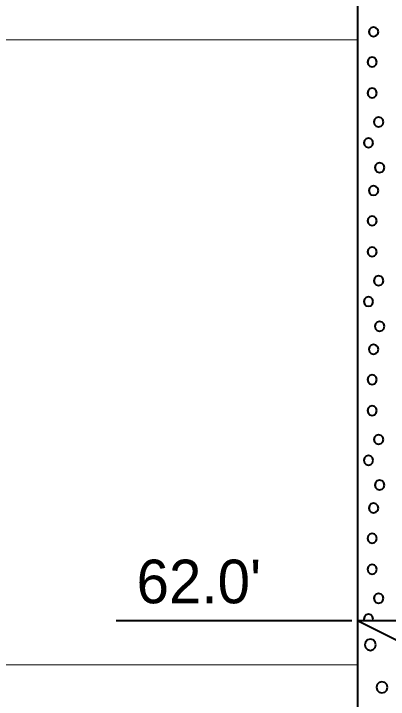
# Model space of a CAD drawing. Extents: x -76 to 974, y -1080 to -735.
# Drawn here: x 752 to 757.99, y -992.64 to -981.67 of the extents above; entities that cross this region are included whole.
import ezdxf

# ---------------------------------------------------------------- set-up
doc = ezdxf.new("R2010")
doc.units = 0
doc.header["$LTSCALE"] = 0.36
doc.layers.add('27', color=7, linetype='Continuous', lineweight=40)
doc.layers.add('7', color=7, linetype='Continuous', lineweight=13)

msp = doc.modelspace()

# ---------------------------------------------------------------- linework, layer by layer
at = {"layer": '27'}
for p, q in [((757.4958, -981.3789), (757.4958, -991.3789)), ((753.6395, -991.3789), (757.4069, -991.3789)), ((757.4958, -991.3789), (759.9958, -991.3789)), ((757.4958, -991.3789), (759.9958, -992.6289)), ((757.4958, -991.3789), (757.4958, -996.3789))]:
    msp.add_line(p, q, dxfattribs=at)
for points in [[(757.8315, -981.9594), (757.8213, -981.9213), (757.7934, -981.8934), (757.7553, -981.8832), (757.7172, -981.8934), (757.6893, -981.9213), (757.6791, -981.9594), (757.6893, -981.9975), (757.7172, -982.0254), (757.7553, -982.0356), (757.7934, -982.0254), (757.8213, -981.9975)], [(757.8086, -982.4438), (757.7984, -982.4057), (757.7705, -982.3778), (757.7324, -982.3676), (757.6943, -982.3778), (757.6664, -982.4057), (757.6562, -982.4438), (757.6664, -982.4819), (757.6943, -982.5097), (757.7324, -982.52), (757.7705, -982.5097), (757.7984, -982.4819)], [(757.8086, -982.9396), (757.7984, -982.9015), (757.7705, -982.8736), (757.7324, -982.8634), (757.6943, -982.8736), (757.6664, -982.9015), (757.6562, -982.9396), (757.6664, -982.9777), (757.6943, -983.0055), (757.7324, -983.0158), (757.7705, -983.0055), (757.7984, -982.9777)], [(757.9116, -983.4023), (757.9014, -983.3642), (757.8735, -983.3363), (757.8354, -983.3261), (757.7973, -983.3363), (757.7694, -983.3642), (757.7592, -983.4023), (757.7694, -983.4404), (757.7973, -983.4683), (757.8354, -983.4785), (757.8735, -983.4683), (757.9014, -983.4404)], [(757.7501, -983.7354), (757.7399, -983.6973), (757.712, -983.6694), (757.6739, -983.6592), (757.6358, -983.6694), (757.608, -983.6973), (757.5977, -983.7354), (757.608, -983.7735), (757.6358, -983.8014), (757.6739, -983.8116), (757.712, -983.8014), (757.7399, -983.7735)], [(757.9277, -984.1316), (757.9175, -984.0935), (757.8896, -984.0656), (757.8515, -984.0554), (757.8134, -984.0656), (757.7855, -984.0935), (757.7753, -984.1316), (757.7855, -984.1697), (757.8134, -984.1975), (757.8515, -984.2078), (757.8896, -984.1975), (757.9175, -984.1697)], [(757.8315, -984.4994), (757.8213, -984.4613), (757.7934, -984.4334), (757.7553, -984.4232), (757.7172, -984.4334), (757.6893, -984.4613), (757.6791, -984.4994), (757.6893, -984.5375), (757.7172, -984.5654), (757.7553, -984.5756), (757.7934, -984.5654), (757.8213, -984.5375)], [(757.8086, -984.9838), (757.7984, -984.9457), (757.7705, -984.9178), (757.7324, -984.9076), (757.6943, -984.9178), (757.6664, -984.9457), (757.6562, -984.9838), (757.6664, -985.0219), (757.6943, -985.0497), (757.7324, -985.06), (757.7705, -985.0497), (757.7984, -985.0219)], [(757.8086, -985.4796), (757.7984, -985.4415), (757.7705, -985.4136), (757.7324, -985.4034), (757.6943, -985.4136), (757.6664, -985.4415), (757.6562, -985.4796), (757.6664, -985.5177), (757.6943, -985.5455), (757.7324, -985.5558), (757.7705, -985.5455), (757.7984, -985.5177)], [(757.9116, -985.9423), (757.9014, -985.9042), (757.8735, -985.8763), (757.8354, -985.8661), (757.7973, -985.8763), (757.7694, -985.9042), (757.7592, -985.9423), (757.7694, -985.9804), (757.7973, -986.0083), (757.8354, -986.0185), (757.8735, -986.0083), (757.9014, -985.9804)], [(757.7501, -986.2754), (757.7399, -986.2373), (757.712, -986.2094), (757.6739, -986.1992), (757.6358, -986.2094), (757.608, -986.2373), (757.5977, -986.2754), (757.608, -986.3135), (757.6358, -986.3414), (757.6739, -986.3516), (757.712, -986.3414), (757.7399, -986.3135)], [(757.9277, -986.6716), (757.9175, -986.6335), (757.8896, -986.6056), (757.8515, -986.5954), (757.8134, -986.6056), (757.7855, -986.6335), (757.7753, -986.6716), (757.7855, -986.7097), (757.8134, -986.7375), (757.8515, -986.7478), (757.8896, -986.7375), (757.9175, -986.7097)], [(757.8315, -987.0394), (757.8213, -987.0013), (757.7934, -986.9734), (757.7553, -986.9632), (757.7172, -986.9734), (757.6893, -987.0013), (757.6791, -987.0394), (757.6893, -987.0775), (757.7172, -987.1054), (757.7553, -987.1156), (757.7934, -987.1054), (757.8213, -987.0775)], [(757.8086, -987.5238), (757.7984, -987.4857), (757.7705, -987.4578), (757.7324, -987.4476), (757.6943, -987.4578), (757.6664, -987.4857), (757.6562, -987.5238), (757.6664, -987.5619), (757.6943, -987.5897), (757.7324, -987.6), (757.7705, -987.5897), (757.7984, -987.5619)], [(757.8086, -988.0196), (757.7984, -987.9815), (757.7705, -987.9536), (757.7324, -987.9434), (757.6943, -987.9536), (757.6664, -987.9815), (757.6562, -988.0196), (757.6664, -988.0577), (757.6943, -988.0855), (757.7324, -988.0958), (757.7705, -988.0855), (757.7984, -988.0577)], [(757.9116, -988.4823), (757.9014, -988.4442), (757.8735, -988.4163), (757.8354, -988.4061), (757.7973, -988.4163), (757.7694, -988.4442), (757.7592, -988.4823), (757.7694, -988.5204), (757.7973, -988.5483), (757.8354, -988.5585), (757.8735, -988.5483), (757.9014, -988.5204)], [(757.7501, -988.8154), (757.7399, -988.7773), (757.712, -988.7494), (757.6739, -988.7392), (757.6358, -988.7494), (757.608, -988.7773), (757.5977, -988.8154), (757.608, -988.8535), (757.6358, -988.8814), (757.6739, -988.8916), (757.712, -988.8814), (757.7399, -988.8535)], [(757.9277, -989.2116), (757.9175, -989.1735), (757.8896, -989.1456), (757.8515, -989.1354), (757.8134, -989.1456), (757.7855, -989.1735), (757.7753, -989.2116), (757.7855, -989.2497), (757.8134, -989.2775), (757.8515, -989.2878), (757.8896, -989.2775), (757.9175, -989.2497)], [(757.8315, -989.5794), (757.8213, -989.5413), (757.7934, -989.5134), (757.7553, -989.5032), (757.7172, -989.5134), (757.6893, -989.5413), (757.6791, -989.5794), (757.6893, -989.6175), (757.7172, -989.6454), (757.7553, -989.6556), (757.7934, -989.6454), (757.8213, -989.6175)], [(757.8086, -990.0638), (757.7984, -990.0257), (757.7705, -989.9978), (757.7324, -989.9876), (757.6943, -989.9978), (757.6664, -990.0257), (757.6562, -990.0638), (757.6664, -990.1019), (757.6943, -990.1297), (757.7324, -990.14), (757.7705, -990.1297), (757.7984, -990.1019)], [(757.8086, -990.5596), (757.7984, -990.5215), (757.7705, -990.4936), (757.7324, -990.4834), (757.6943, -990.4936), (757.6664, -990.5215), (757.6562, -990.5596), (757.6664, -990.5977), (757.6943, -990.6255), (757.7324, -990.6358), (757.7705, -990.6255), (757.7984, -990.5977)], [(757.9116, -991.0223), (757.9014, -990.9842), (757.8735, -990.9563), (757.8354, -990.9461), (757.7973, -990.9563), (757.7694, -990.9842), (757.7592, -991.0223), (757.7694, -991.0604), (757.7973, -991.0883), (757.8354, -991.0985), (757.8735, -991.0883), (757.9014, -991.0604)], [(757.7501, -991.3554), (757.7399, -991.3173), (757.712, -991.2894), (757.6739, -991.2792), (757.6358, -991.2894), (757.608, -991.3173), (757.5977, -991.3554), (757.6041, -991.3789), (757.7438, -991.3789)], [(757.7934, -991.767), (757.7815, -991.7226), (757.7489, -991.69), (757.7045, -991.6781), (757.66, -991.69), (757.6275, -991.7226), (757.6156, -991.767), (757.6275, -991.8115), (757.66, -991.844), (757.7045, -991.8559), (757.7489, -991.844), (757.7815, -991.8115)], [(757.9777, -992.4459), (757.9658, -992.4014), (757.9333, -992.3689), (757.8888, -992.357), (757.8444, -992.3689), (757.8118, -992.4014), (757.7999, -992.4459), (757.8118, -992.4903), (757.8444, -992.5229), (757.8888, -992.5348), (757.9333, -992.5229), (757.9658, -992.4903)]]:
    msp.add_lwpolyline(points, close=True, dxfattribs=at)
at = {"layer": '7'}
for p, q in [((726.8972, -982.09), (757.4958, -982.09)), ((726.8972, -992.09), (757.4958, -992.09))]:
    msp.add_line(p, q, dxfattribs=at)

# ---------------------------------------------------------------- texts
at = {"layer": '27'}
msp.add_text("62.0'", height=0.6976, dxfattribs=at).set_placement((753.9635, -991.1025))

doc.saveas('drawing.dxf')
